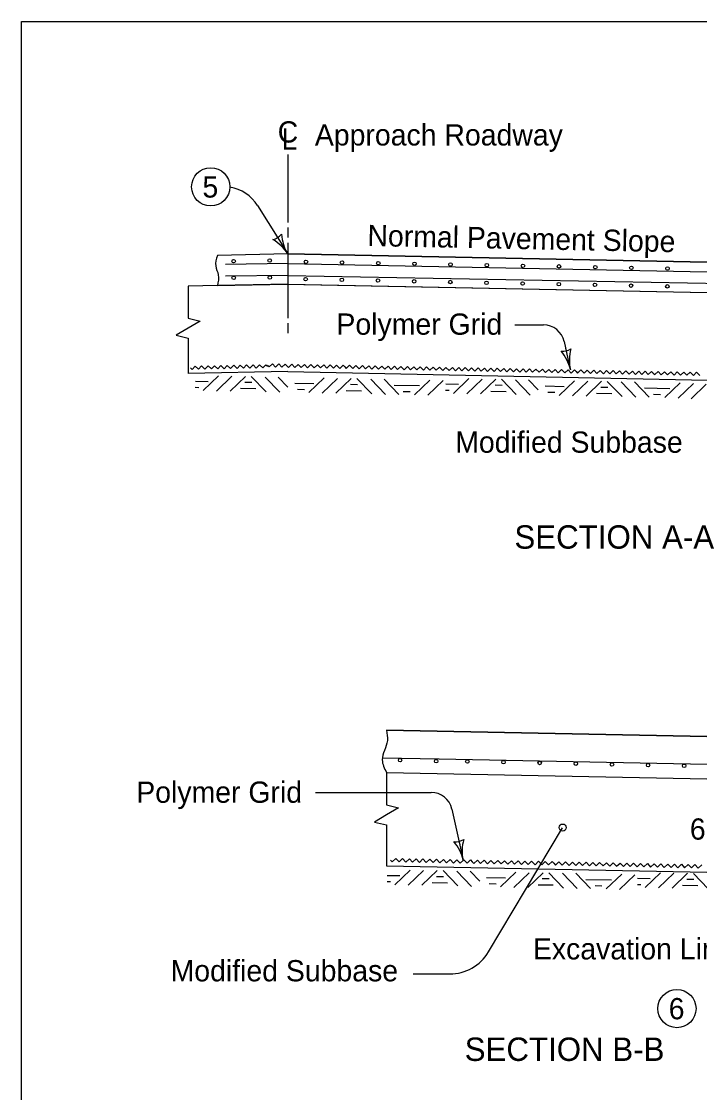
# Model space of a CAD drawing. Extents: x 8925 to 81668, y 4369 to 11918.
# Drawn here: x 17333 to 17971, y 8936 to 9944 of the extents above; entities that cross this region are included whole.
import ezdxf

# ---------------------------------------------------------------- set-up
doc = ezdxf.new("R2010")
doc.units = 0
for name, color, linetype in [('dsnShtPlotShapeBatchPrint', 7, 'Continuous'), ('dsnStdBorder', 7, 'Continuous'), ('SheetBorder', 7, 'Continuous')]:
    doc.layers.add(name, color=color, linetype=linetype)

msp = doc.modelspace()

# ---------------------------------------------------------------- linework, layer by layer
at = {"layer": 'dsnShtPlotShapeBatchPrint'}
msp.add_line((18314.8, 9691.1), (17583.2, 9704.6), dxfattribs=at)
at = {"layer": 'dsnStdBorder'}
for p, q in [((17554.7, 9770.7), (17583.3, 9725.2)), ((17583.3, 9725.2), (17516.9, 9723.8)), ((17583.3, 9725.2), (17516.9, 9723.8)), ((18293.5, 9710.9), (17583.3, 9725.2)), ((17583.3, 9725.2), (18293.5, 9710.9)), ((17583.2, 9716.3), (17524.7, 9715.1)), ((17583.3, 9716.2), (18315, 9701.5)), ((17583.2, 9704.9), (17524.7, 9704.2)), ((17516.9, 9695.5), (17489.3, 9694.9)), ((17489.3, 9694.9), (17489.3, 9664.7)), ((17516.9, 9695.5), (17582.7, 9696.8)), ((17583.8, 9696.8), (17516.9, 9695.5)), ((17582.7, 9696.8), (17583.3, 9696.8)), ((17582.7, 9696.8), (18331.8, 9681.8)), ((17583.3, 9696.8), (17583.8, 9696.8)), ((17583.8, 9696.8), (18331.8, 9681.8)), ((17489.3, 9664.7), (17500.7, 9661.8)), ((17500.7, 9661.8), (17489.3, 9655.2)), ((17489.3, 9655.2), (17478, 9648.6)), ((17797, 9658.3), (17823.8, 9658.3)), ((17478, 9648.6), (17489.3, 9645.8)), ((17489.3, 9645.8), (17489.3, 9612.5)), ((17843.3, 9642.6), (17849.1, 9616.2)), ((17844.7, 9636.1), (17845.9, 9631)), ((17583.3, 9614.4), (17489.3, 9612.5)), ((17517.9, 9610.4), (17503.5, 9596.6)), ((17530.4, 9610), (17516, 9596.1)), ((17543.4, 9609.9), (17529, 9596.1)), ((17548.8, 9609.8), (17562.7, 9595.4)), ((17561.8, 9609.3), (17575.7, 9594.9)), ((17574.3, 9609.3), (17583.4, 9599.8)), ((17583.3, 9614.4), (18399.8, 9598)), ((17617.5, 9608.4), (17603.1, 9594.6)), ((17629.9, 9608), (17615.5, 9594.1)), ((17642.9, 9607.9), (17628.5, 9594.1)), ((17648.3, 9607.8), (17662.2, 9593.4)), ((17661.3, 9607.3), (17675.2, 9592.9)), ((17673.8, 9607.3), (17687.6, 9592.9)), ((17717, 9606.4), (17702.6, 9592.6)), ((17729.5, 9606), (17715, 9592.1)), ((17753.5, 9607.8), (17739.1, 9593.9)), ((17766, 9607.3), (17751.6, 9593.5)), ((17779, 9607.3), (17764.6, 9593.4)), ((17784.4, 9607.2), (17798.3, 9592.8)), ((17797.4, 9606.7), (17811.3, 9592.3)), ((17809.9, 9606.7), (17819, 9597.2)), ((17853.1, 9605.8), (17838.7, 9591.9)), ((17865.5, 9605.3), (17851.1, 9591.5)), ((17878.5, 9605.3), (17864.1, 9591.4)), ((17883.9, 9605.2), (17897.8, 9590.8)), ((17896.9, 9604.7), (17910.8, 9590.3)), ((17909.4, 9604.7), (17923.2, 9590.3)), ((17952.6, 9603.8), (17938.2, 9590)), ((17965.1, 9603.3), (17950.6, 9589.5)), ((17977.1, 9602.6), (17962.7, 9588.7)), ((18049.1, 9269.5), (17676.1, 9277)), ((17676.1, 9277), (18049.1, 9269.5)), ((17725.6, 9249.6), (17672.2, 9250.6)), ((18027, 9243.5), (17725.6, 9249.6)), ((17676.1, 9237), (18049.1, 9229.5)), ((17676.1, 9237), (18049.1, 9229.5)), ((17676.1, 9236.7), (17676.1, 9206.5)), ((17609.3, 9218.3), (17718.1, 9218.3)), ((17676.1, 9206.5), (17687.5, 9203.6)), ((17676.1, 9197), (17664.8, 9190.4)), ((17687.5, 9203.6), (17676.1, 9197)), ((17737.6, 9202.6), (17748.3, 9154.4)), ((17664.8, 9190.4), (17676.1, 9187.6)), ((17676.1, 9187.6), (17676.1, 9149.2)), ((17772.1, 9068.1), (17841.9, 9184.9)), ((17743.9, 9174.3), (17745, 9169.2)), ((17676.1, 9149.2), (18145, 9139.8)), ((17698.4, 9145.2), (17684, 9131.4)), ((17710.8, 9144.7), (17696.4, 9130.9)), ((17723.9, 9144.7), (17709.4, 9130.9)), ((17729.3, 9144.6), (17743.1, 9130.2)), ((17742.3, 9144.1), (17756.1, 9129.7)), ((17754.7, 9144.1), (17763.8, 9134.6)), ((17797.9, 9143.2), (17783.5, 9129.4)), ((17810.4, 9142.7), (17796, 9128.9)), ((17823.4, 9142.7), (17809, 9128.9)), ((17828.8, 9142.6), (17842.7, 9128.2)), ((17841.8, 9142.1), (17855.7, 9127.7)), ((17854.3, 9142.1), (17868.1, 9127.7)), ((17897.5, 9141.2), (17883, 9127.4)), ((17909.9, 9140.7), (17895.5, 9126.9)), ((17934, 9142.6), (17919.6, 9128.7)), ((17946.4, 9142.1), (17932, 9128.3)), ((17959.5, 9142.1), (17945, 9128.2)), ((17964.9, 9142), (17978.7, 9127.5)), ((17701.3, 9047.4), (17735.6, 9047.4))]:
    msp.add_line(p, q, dxfattribs=at)
for points in [[(17583.3, 9818.6), (17583.3, 9754.6)], [(17583.3, 9749.9), (17583.3, 9740.5)], [(17583.3, 9735.7), (17583.3, 9664.8)], [(17582.7, 9696.8), (17582.7, 9696.8)], [(17583.8, 9696.8), (17583.8, 9696.8)], [(17583.3, 9660.1), (17583.3, 9650.6)], [(17491.6, 9618), (17493.1, 9616.5), (17496.1, 9619.6), (17499.2, 9616.6), (17502.1, 9619.7), (17505.2, 9616.7), (17508.2, 9619.8), (17511.3, 9616.9), (17514.2, 9619.9), (17517.3, 9617), (17520.3, 9620.1), (17523.4, 9617.1), (17526.3, 9620.2), (17529.4, 9617.2), (17532.4, 9620.3), (17535.5, 9617.3), (17538.4, 9620.4), (17541.5, 9617.5), (17544.5, 9620.6), (17547.6, 9617.6), (17550.5, 9620.7), (17553.6, 9617.7), (17556.6, 9620.8), (17559.7, 9617.8), (17562.6, 9620.9), (17564.2, 9619.4)], [(17564.2, 9620.3), (17565.6, 9618.8), (17568.7, 9621.7), (17571.7, 9618.6), (17574.8, 9621.6), (17577.7, 9618.5), (17580.8, 9621.5), (17583.8, 9618.4), (17586.9, 9621.4), (17589.8, 9618.3), (17592.9, 9621.2), (17595.9, 9618.1), (17599, 9621.1), (17601.9, 9618), (17605, 9621), (17608, 9617.9), (17611.1, 9620.9), (17614, 9617.8), (17617.1, 9620.7), (17620.1, 9617.7), (17623.2, 9620.6), (17626.1, 9617.5), (17629.2, 9620.5), (17632.2, 9617.4), (17635.3, 9620.4), (17636.8, 9618.8)], [(17636.8, 9618.8), (17638.2, 9617.3), (17641.3, 9620.3), (17644.3, 9617.2), (17647.4, 9620.1), (17650.3, 9617.1), (17653.4, 9620), (17656.4, 9616.9), (17659.5, 9619.9), (17662.4, 9616.8), (17665.5, 9619.8), (17668.5, 9616.7), (17671.6, 9619.6), (17674.5, 9616.6), (17677.6, 9619.5), (17680.6, 9616.4), (17683.7, 9619.4), (17686.6, 9616.3), (17689.7, 9619.3), (17692.7, 9616.2), (17695.8, 9619.2), (17698.7, 9616.1), (17701.8, 9619), (17704.8, 9616), (17707.9, 9618.9), (17709.3, 9617.4)], [(17709.3, 9617.4), (17710.8, 9615.8), (17713.9, 9618.8), (17716.9, 9615.7), (17720, 9618.7), (17722.9, 9615.6), (17726, 9618.6), (17729, 9615.5), (17732.1, 9618.4), (17735, 9615.4), (17738.1, 9618.3), (17741.1, 9615.2), (17744.1, 9618.2), (17747.1, 9615.1), (17750.2, 9618.1), (17753.2, 9615), (17756.2, 9618), (17759.2, 9614.9), (17762.3, 9617.8), (17765.3, 9614.7), (17768.3, 9617.7), (17771.3, 9614.6), (17774.4, 9617.6), (17777.4, 9614.5), (17780.4, 9617.5), (17781.9, 9615.9)], [(17781.9, 9615.9), (17783.4, 9614.4), (17786.5, 9617.3), (17789.5, 9614.3), (17792.5, 9617.2), (17795.5, 9614.1), (17798.6, 9617.1), (17801.5, 9614), (17804.6, 9617), (17807.6, 9613.9), (17810.7, 9616.9), (17813.6, 9613.8), (17816.7, 9616.7), (17819.7, 9613.7), (17822.8, 9616.6), (17825.7, 9613.5), (17828.8, 9616.5), (17831.8, 9613.4), (17834.9, 9616.4), (17837.8, 9613.3), (17840.9, 9616.3), (17843.9, 9613.2), (17847, 9616.1), (17849.9, 9613), (17853, 9616), (17854.5, 9614.5)], [(17854.5, 9614.5), (17856, 9612.9), (17859.1, 9615.9), (17862, 9612.8), (17865.1, 9615.8), (17868.1, 9612.7), (17871.2, 9615.6), (17874.1, 9612.6), (17877.2, 9615.5), (17880.2, 9612.4), (17883.3, 9615.4), (17886.2, 9612.3), (17889.3, 9615.3), (17892.3, 9612.2), (17895.4, 9615.2), (17898.3, 9612.1), (17901.4, 9615), (17904.4, 9612), (17907.5, 9614.9), (17910.4, 9611.8), (17913.5, 9614.8), (17916.5, 9611.7), (17919.6, 9614.7), (17922.5, 9611.6), (17925.6, 9614.6), (17927.1, 9613)], [(17927.1, 9613), (17928.6, 9611.5), (17931.7, 9614.4), (17934.6, 9611.3), (17937.7, 9614.3), (17940.7, 9611.2), (17943.8, 9614.2), (17946.7, 9611.1), (17949.8, 9614.1), (17952.8, 9611), (17955.9, 9613.9), (17958.8, 9610.9), (17961.9, 9613.8), (17964.9, 9610.7), (17968, 9613.7), (17970.9, 9610.6)], [(17496.1, 9599.6), (17499.4, 9599.5)], [(17496.2, 9605.4), (17508.3, 9605.2)], [(17542.7, 9604.4), (17549.3, 9604.3)], [(17589.7, 9603.5), (17607.8, 9603.2)], [(17642.3, 9602.4), (17648.8, 9602.3)], [(17683.3, 9601.6), (17707.3, 9601.2)], [(17731.8, 9602.8), (17743.9, 9602.5)], [(17778.3, 9601.8), (17784.9, 9601.7)], [(17825.3, 9600.9), (17843.4, 9600.5)], [(17877.9, 9599.8), (17884.4, 9599.7)], [(17538.8, 9598.7), (17553, 9598.4)], [(17592.4, 9597.7), (17598.9, 9597.5)], [(17638.3, 9596.7), (17652.5, 9596.4)], [(17691.9, 9595.7), (17698.4, 9595.5)], [(17731.7, 9597), (17735, 9596.9)], [(17774.4, 9596), (17788.6, 9595.7)], [(17828, 9595), (17834.5, 9594.9)], [(17873.9, 9594), (17888.1, 9593.7)], [(17918.9, 9599), (17942.9, 9598.5)], [(17927.5, 9593), (17934, 9592.9)], [(17679.9, 9154.6), (17681.5, 9152.9), (17684.8, 9156.1), (17687.9, 9152.8), (17691.2, 9155.9), (17694.3, 9152.7), (17697.6, 9155.8), (17700.7, 9152.5), (17704, 9155.7), (17707.1, 9152.4), (17710.4, 9155.6), (17713.5, 9152.3), (17716.8, 9155.4), (17719.9, 9152.2), (17723.2, 9155.3), (17726.3, 9152), (17729.6, 9155.2), (17732.7, 9151.9), (17736, 9155), (17739.1, 9151.8), (17742.4, 9154.9), (17745.5, 9151.7), (17748.8, 9154.8), (17751.9, 9151.5), (17755.2, 9154.7), (17756.7, 9153)], [(17756.7, 9153), (17758.3, 9151.4), (17761.6, 9154.5), (17764.7, 9151.3), (17768, 9154.4), (17771.1, 9151.1), (17774.4, 9154.3), (17777.5, 9151), (17780.8, 9154.1), (17783.9, 9150.9), (17787.2, 9154), (17790.3, 9150.8), (17793.6, 9153.9), (17796.7, 9150.6), (17800, 9153.8), (17803.1, 9150.5), (17806.4, 9153.6), (17809.5, 9150.4), (17812.7, 9153.5), (17815.9, 9150.2), (17819.1, 9153.4), (17822.3, 9150.1), (17825.5, 9153.2), (17828.7, 9150), (17831.9, 9153.1), (17833.5, 9151.5)], [(17833.5, 9151.5), (17835.1, 9149.9), (17838.3, 9153), (17841.5, 9149.7), (17844.7, 9152.9), (17847.9, 9149.6), (17851.1, 9152.7), (17854.3, 9149.5), (17857.5, 9152.6), (17860.7, 9149.3), (17863.9, 9152.5), (17867.1, 9149.2), (17870.3, 9152.3), (17873.5, 9149.1), (17876.7, 9152.2), (17879.9, 9149), (17883.1, 9152.1), (17886.3, 9148.8), (17889.5, 9152), (17892.7, 9148.7), (17895.9, 9151.8), (17899.1, 9148.6), (17902.3, 9151.7), (17905.5, 9148.4), (17908.7, 9151.6), (17910.3, 9149.9)], [(17910.3, 9149.8), (17911.9, 9148.2), (17915.2, 9151.3), (17918.3, 9148.1), (17921.6, 9151.2), (17924.7, 9148), (17928, 9151.1), (17931.1, 9147.8), (17934.4, 9151), (17937.5, 9147.7), (17940.8, 9150.8), (17943.9, 9147.6), (17947.2, 9150.7), (17950.3, 9147.4), (17953.6, 9150.6), (17956.7, 9147.3), (17960, 9150.4), (17963.1, 9147.2), (17966.4, 9150.3), (17969.5, 9147.1), (17972.8, 9150.2)], [(17676.7, 9140.2), (17688.7, 9139.9)], [(17723.2, 9139.2), (17729.7, 9139.1)], [(17770.2, 9138.3), (17788.2, 9137.9)], [(17822.7, 9137.2), (17829.2, 9137.1)], [(17863.7, 9136.4), (17887.8, 9135.9)], [(17912.3, 9137.5), (17924.3, 9137.3)], [(17958.8, 9136.6), (17965.3, 9136.5)], [(17676.6, 9134.4), (17679.8, 9134.3)], [(17719.2, 9133.4), (17733.4, 9133.2)], [(17772.8, 9132.4), (17779.4, 9132.3)], [(17818.8, 9131.4), (17833, 9131.2)], [(17872.4, 9130.5), (17878.9, 9130.3)], [(17912.2, 9131.7), (17915.4, 9131.7)], [(17954.8, 9130.8), (17969, 9130.5)]]:
    msp.add_lwpolyline(points, dxfattribs=at)
for centre, radius in [((17510.7, 9788.3), 18), ((17566.2, 9719), 1.65), ((17532.2, 9718.3), 1.65), ((17600.3, 9717.7), 1.65), ((17634.3, 9717.1), 1.65), ((17668.4, 9716.5), 1.65), ((17702.4, 9715.9), 1.65), ((17736.4, 9715.2), 1.65), ((17770.5, 9714.6), 1.65), ((17804.5, 9714), 1.65), ((17838.5, 9713.4), 1.65), ((17872.6, 9712.7), 1.65), ((17906.6, 9712.1), 1.65), ((17940.6, 9711.5), 1.65), ((17532.3, 9702.7), 1.65), ((17566.3, 9703), 1.65), ((17600, 9701.4), 1.65), ((17634.1, 9700.7), 1.65), ((17668.1, 9700.1), 1.65), ((17702.1, 9699.4), 1.65), ((17736.2, 9698.7), 1.65), ((17770.2, 9698), 1.65), ((17804.2, 9697.3), 1.65), ((17838.3, 9696.7), 1.65), ((17872.3, 9696), 1.65), ((17906.3, 9695.3), 1.65), ((17940.4, 9694.6), 1.65), ((17688.9, 9248.6), 1.65), ((17722.9, 9247.7), 1.65), ((17752.2, 9247.4), 1.65), ((17786.2, 9246.7), 1.65), ((17820.2, 9246), 1.65), ((17854.3, 9245.3), 1.65), ((17888.3, 9244.6), 1.65), ((17922.3, 9243.9), 1.65), ((17956.3, 9243.3), 1.65), ((17841.9, 9185.2), 3.31), ((17949.4, 9014.8), 18)]:
    msp.add_circle(centre, radius, dxfattribs=at)
for centre, radius, start, end in [((17522.7, 9750.6), 37.8, 32.09, 80.8776), ((17565.4, 9753.7), 15.5, 284.3569, 319.8236), ((17565.4, 9753.7), 15.5, 284.3569, 319.8236), ((17617.3, 9746.5), 40.2, 184.0178, 212.0903), ((17617.3, 9746.5), 40.2, 184.0178, 212.0903), ((17549.2, 9703.8), 40.2, 32.0903, 60.1628), ((17549.2, 9703.8), 40.2, 32.0903, 60.1628), ((17823.8, 9638.3), 20, 12.4314, 90), ((17841.9, 9649.1), 15.5, 264.685, 300.1517), ((17809.9, 9607.6), 40.2, 12.4183, 40.4908), ((17888.4, 9624.9), 40.2, 164.3459, 192.4183), ((17718.1, 9198.3), 20, 12.4313, 90), ((17741, 9187.3), 15.5, 264.685, 300.1517), ((17709, 9145.8), 40.2, 12.4183, 40.4908), ((17787.5, 9163.1), 40.2, 164.3459, 192.4183), ((17735.6, 9089.9), 42.5, 270, 329.1249)]:
    msp.add_arc(centre, radius, start, end, dxfattribs=at)
for points in [[(17516.9, 9723.8), (17515.4, 9713.8), (17517.8, 9705.6), (17516.9, 9695.5)], [(17516.9, 9723.8), (17515.4, 9713.8), (17517.8, 9705.6), (17516.9, 9695.5)], [(17676.1, 9277), (17676.9, 9267), (17672.1, 9248.9), (17676.1, 9237)], [(17676.1, 9277), (17676.9, 9267), (17672.1, 9248.9), (17676.1, 9237)]]:
    msp.add_spline(points, degree=3, dxfattribs=at)
at = {"layer": 'SheetBorder'}
msp.add_lwpolyline([(17332.5, 9944), (20467.5, 9944), (20467.5, 7924), (17332.5, 7924)], close=True, dxfattribs=at)

# ---------------------------------------------------------------- texts
at = {"layer": 'dsnShtPlotShapeBatchPrint'}
for s, height, p in [('C', 20, (17573.7, 9830)), ('L', 20, (17577.3, 9823.3)), ('Approach Roadway', 20, (17608.7, 9827.2)), ('5', 20, (17502.9, 9778.2)), ('Polymer Grid', 20, (17629, 9649.1)), ('Modified Subbase', 20, (17740.8, 9538)), ('SECTION A-A', 22, (17796.5, 9447.7)), ('Polymer Grid', 20, (17440.6, 9208.5)), ('6"', 20, (17961.6, 9173.8)), ('Excavation Limits', 20, (17813.9, 9061)), ('Modified Subbase', 20, (17472.9, 9040.4)), ('6', 20, (17941.7, 9004.7)), ('SECTION B-B', 22, (17749.7, 8965.5))]:
    msp.add_text(s, height=height, dxfattribs=at).set_placement(p)
msp.add_text('Normal Pavement Slope', height=20, rotation=358.8502, dxfattribs=at).set_placement((17658, 9732.6))

doc.saveas('drawing.dxf')
